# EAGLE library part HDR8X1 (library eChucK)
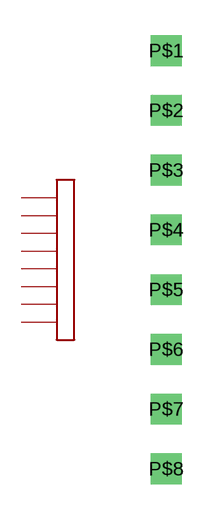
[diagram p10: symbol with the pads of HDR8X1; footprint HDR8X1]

Designator prefix H

## HDR8X1  [HDR8X1]
P$1  P$1
P$2  P$2
P$3  P$3
P$4  P$4
P$5  P$5
P$6  P$6
P$7  P$7
P$8  P$8

## Footprint HDR8X1 (pad centres in mm)
drill 0.8 square: P$1 0,8.89; P$2 0,6.35; P$3 0,3.81; P$4 0,1.27; P$5 0,-1.27; P$6 0,-3.81; P$7 0,-6.35; P$8 0,-8.89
